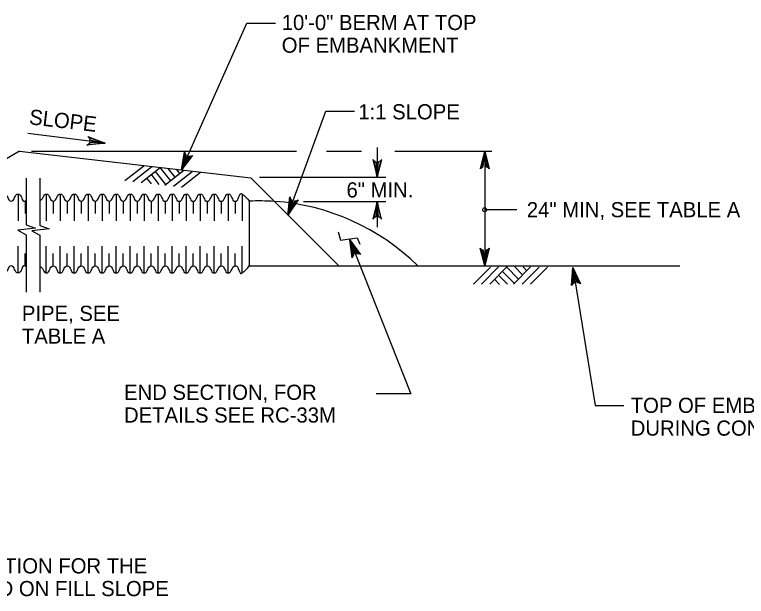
# Model space of a CAD drawing. Extents: x 636462 to 637367, y 299944 to 300538.
# Drawn here: x 636777.1 to 636921.8, y 300064.4 to 300179.4 of the extents above; entities that cross this region are included whole.
import ezdxf

# ---------------------------------------------------------------- set-up
doc = ezdxf.new("R2010")
doc.units = 0
doc.layers.add('1', color=7, linetype='Continuous')
doc.layers.add('Default', color=7, linetype='Continuous')

# ---------------------------------------------------------------- blocks, each defined once
blk = doc.blocks.new('SC9446')
at = {"layer": 'Default'}
blk.add_line((0, 0), (0, 0), dxfattribs=at)

msp = doc.modelspace()

# ---------------------------------------------------------------- linework, layer by layer
at = {"layer": '1'}
msp.add_line((636843.37, 300134.93), (636855.42, 300104.46), dxfattribs=at)
msp.add_lwpolyline([(636841.04, 300136.46), (636841.54, 300134.84), (636844.79, 300135.33), (636845.36, 300134.04)], dxfattribs=at)
at = {"layer": 'Default'}
for p, q in [((636810.07, 300148.74), (636823.01, 300177.78)), ((636823.01, 300177.78), (636828.69, 300177.78)), ((636778.09, 300152.42), (636723.37, 300120.94)), ((636778.09, 300152.42), (636823.79, 300147.16)), ((636780.41, 300152.42), (636832.84, 300152.42)), ((636838.75, 300152.42), (636845.69, 300152.42)), ((636848.79, 300153.14), (636848.79, 300147.3)), ((636852.29, 300152.42), (636871.44, 300152.42)), ((636870.03, 300152.42), (636870.03, 300129.76)), ((636798.92, 300146.61), (636802.66, 300149.57)), ((636800.49, 300146.43), (636804.24, 300149.41)), ((636802.11, 300146.24), (636805.86, 300149.22)), ((636804.88, 300148.44), (636806.94, 300145.85)), ((636805.79, 300149.23), (636807.9, 300146.58)), ((636806.77, 300145.7), (636810.55, 300148.7)), ((636807.41, 300149.04), (636808.78, 300147.32)), ((636808.48, 300145.51), (636812.2, 300148.45)), ((636809.05, 300148.85), (636809.71, 300148.03)), ((636810.1, 300145.32), (636813.82, 300148.27)), ((636779.38, 300147.1), (636779.38, 300137.86)), ((636782.11, 300147.1), (636782.11, 300137.76)), ((636803.17, 300147.09), (636804.07, 300145.96)), ((636804.08, 300147.8), (636805.64, 300145.83)), ((636823.79, 300147.16), (636841.18, 300129.76)), ((636825.49, 300147.3), (636850.48, 300147.3)), ((636777.8, 300143.94), (636777.8, 300138.68)), ((636783.34, 300143.94), (636783.34, 300138.68)), ((636786.11, 300143.94), (636786.11, 300138.68)), ((636788.88, 300143.94), (636788.88, 300138.68)), ((636791.65, 300143.94), (636791.65, 300138.68)), ((636794.42, 300143.94), (636794.42, 300138.68)), ((636797.19, 300143.94), (636797.19, 300138.68)), ((636799.96, 300143.94), (636799.96, 300138.68)), ((636802.73, 300143.94), (636802.73, 300138.68)), ((636805.5, 300143.94), (636805.5, 300138.68)), ((636808.27, 300143.94), (636808.27, 300138.68)), ((636811.04, 300143.94), (636811.04, 300138.68)), ((636813.81, 300143.94), (636813.81, 300138.68)), ((636816.58, 300143.94), (636816.58, 300138.68)), ((636819.35, 300143.94), (636819.35, 300138.68)), ((636822.12, 300143.94), (636822.12, 300138.68)), ((636779.19, 300142.56), (636779.19, 300140.14)), ((636784.73, 300142.56), (636784.73, 300140.14)), ((636787.5, 300142.56), (636787.5, 300140.14)), ((636790.27, 300142.56), (636790.27, 300140.14)), ((636793.04, 300142.56), (636793.04, 300140.14)), ((636795.81, 300142.56), (636795.81, 300140.14)), ((636798.58, 300142.56), (636798.58, 300140.14)), ((636801.35, 300142.56), (636801.35, 300140.14)), ((636804.12, 300142.56), (636804.12, 300140.14)), ((636806.89, 300142.55), (636806.89, 300140.14)), ((636809.66, 300142.55), (636809.66, 300140.14)), ((636812.43, 300142.55), (636812.43, 300140.14)), ((636815.2, 300142.55), (636815.2, 300140.14)), ((636817.96, 300142.55), (636817.96, 300140.14)), ((636820.73, 300142.55), (636820.73, 300140.14)), ((636823.5, 300142.55), (636823.5, 300129.76)), ((636823.5, 300142.55), (636823.5, 300129.76)), ((636834.21, 300142.5), (636850.48, 300142.5)), ((636848.79, 300142.5), (636848.79, 300137.4)), ((636876.41, 300140.85), (636870.03, 300140.85)), ((636779.38, 300135.93), (636779.38, 300124.53)), ((636782.11, 300135.83), (636782.11, 300124.53)), ((636777.8, 300128.38), (636777.8, 300133.64)), ((636783.34, 300128.38), (636783.34, 300133.64)), ((636786.11, 300128.38), (636786.11, 300133.64)), ((636788.88, 300128.38), (636788.88, 300133.64)), ((636791.65, 300128.38), (636791.65, 300133.64)), ((636794.42, 300128.38), (636794.42, 300133.64)), ((636797.19, 300128.38), (636797.19, 300133.64)), ((636799.96, 300128.38), (636799.96, 300133.64)), ((636802.73, 300128.38), (636802.73, 300133.64)), ((636805.5, 300128.38), (636805.5, 300133.64)), ((636808.27, 300128.38), (636808.27, 300133.64)), ((636811.04, 300128.38), (636811.04, 300133.64)), ((636813.81, 300128.38), (636813.81, 300133.64)), ((636816.58, 300128.38), (636816.58, 300133.64)), ((636819.35, 300128.38), (636819.35, 300133.64)), ((636822.12, 300128.38), (636822.12, 300133.64)), ((636779.19, 300129.76), (636779.19, 300132.18)), ((636784.73, 300129.76), (636784.73, 300132.18)), ((636787.5, 300129.76), (636787.5, 300132.18)), ((636790.27, 300129.76), (636790.27, 300132.18)), ((636793.04, 300129.76), (636793.04, 300132.18)), ((636795.81, 300129.76), (636795.81, 300132.18)), ((636798.58, 300129.76), (636798.58, 300132.18)), ((636801.35, 300129.76), (636801.35, 300132.18)), ((636804.12, 300129.76), (636804.12, 300132.18)), ((636806.89, 300129.76), (636806.89, 300132.18)), ((636809.66, 300129.76), (636809.66, 300132.18)), ((636812.43, 300129.76), (636812.43, 300132.18)), ((636815.2, 300129.76), (636815.2, 300132.18)), ((636817.96, 300129.76), (636817.96, 300132.18)), ((636820.73, 300129.76), (636820.73, 300132.18)), ((636823.5, 300129.76), (636841.18, 300129.76)), ((636841.18, 300129.76), (636908.62, 300129.76)), ((636842.95, 300129.76), (636852.95, 300129.76)), ((636867.81, 300126.16), (636871.18, 300129.53)), ((636869.39, 300126.16), (636872.77, 300129.55)), ((636871.02, 300126.16), (636874.41, 300129.55)), ((636874.33, 300129.55), (636876.73, 300127.15)), ((636875.71, 300126.16), (636879.12, 300129.56)), ((636875.97, 300129.55), (636877.53, 300127.99)), ((636877.43, 300126.16), (636880.79, 300129.51)), ((636877.62, 300129.55), (636878.36, 300128.8)), ((636879.07, 300126.16), (636882.42, 300129.51)), ((636872.79, 300127.93), (636874.57, 300126.16)), ((636873.52, 300128.66), (636875.86, 300126.32)), ((636871.98, 300127.12), (636872.99, 300126.1)), ((636855.42, 300104.46), (636848.58, 300104.46))]:
    msp.add_line(p, q, dxfattribs=at)
for points in [[(636831.14, 300139.79), (636838.61, 300160.33), (636844.28, 300160.33)], [(636794.98, 300154.05), (636779.69, 300155.91)], [(636791.85, 300155.08), (636791.61, 300155.33), (636794.98, 300154.05), (636791.85, 300155.08), (636792, 300154.68), (636794.98, 300154.05), (636791.94, 300154.16), (636791.72, 300153.81), (636794.98, 300154.05), (636791.4, 300153.6), (636791.72, 300153.81)], [(636811.97, 300151.43), (636812.29, 300151.58), (636810.07, 300148.74), (636811.97, 300151.43), (636811.55, 300151.4), (636810.07, 300148.74), (636811.07, 300151.61), (636810.8, 300151.93), (636810.07, 300148.74), (636810.68, 300152.29), (636810.8, 300151.93)], [(636869.39, 300149.19), (636869.17, 300148.92), (636870.03, 300152.42), (636869.39, 300149.19), (636869.76, 300149.39), (636870.03, 300152.42), (636870.29, 300149.39), (636870.66, 300149.21), (636870.03, 300152.42), (636870.92, 300148.93), (636870.66, 300149.21)], [(636848.16, 300150.53), (636847.93, 300150.8), (636848.79, 300147.3), (636848.16, 300150.53), (636848.53, 300150.33), (636848.79, 300147.3), (636849.05, 300150.33), (636849.43, 300150.51), (636848.79, 300147.3), (636849.68, 300150.79), (636849.43, 300150.51)], [(636832.84, 300142.62), (636833.14, 300142.79), (636831.14, 300139.79), (636832.84, 300142.62), (636832.42, 300142.56), (636831.14, 300139.79), (636831.93, 300142.73), (636831.64, 300143.03), (636831.14, 300139.79), (636831.49, 300143.38), (636831.64, 300143.03)], [(636849.43, 300139.27), (636849.65, 300139), (636848.79, 300142.5), (636849.43, 300139.27), (636849.06, 300139.47), (636848.79, 300142.5), (636848.53, 300139.47), (636848.16, 300139.29), (636848.79, 300142.5), (636847.91, 300139.01), (636848.16, 300139.29)], [(636779.38, 300137.86), (636781.2, 300137.19), (636777.76, 300136.79), (636779.38, 300135.93)], [(636782.11, 300137.76), (636783.93, 300137.09), (636780.49, 300136.69), (636782.11, 300135.83)], [(636843.95, 300131.68), (636843.84, 300131.35), (636843.37, 300134.93), (636843.95, 300131.68), (636844.22, 300132), (636843.37, 300134.93), (636844.71, 300132.2), (636845.12, 300132.16), (636843.37, 300134.93), (636845.46, 300131.99), (636845.12, 300132.16)], [(636870.67, 300132.99), (636870.89, 300133.26), (636870.03, 300129.76), (636870.67, 300132.99), (636870.29, 300132.8), (636870.03, 300129.76), (636869.77, 300132.79), (636869.39, 300132.97), (636870.03, 300129.76), (636869.14, 300133.25), (636869.39, 300132.97)], [(636887.39, 300126.17), (636887.22, 300125.86), (636887.45, 300129.46), (636887.39, 300126.17), (636887.72, 300126.43), (636887.45, 300129.46), (636888.24, 300126.52), (636888.64, 300126.41), (636887.45, 300129.46), (636888.94, 300126.18), (636888.64, 300126.41)], [(636887.44, 300129.47), (636891.87, 300102.15), (636897.54, 300102.15)]]:
    msp.add_lwpolyline(points, dxfattribs=at)
msp.add_circle((636870.03, 300140.85), 0.391, dxfattribs=at)
for start, end in [(86.2211, 92.5748), (45.3846, 86.2211)]:
    msp.add_arc((636825.51, 300098.04), 44.56, start, end, dxfattribs=at)
for points in [[(636764.07, 300143.83), (636764.5, 300143.4), (636764.92, 300142.98), (636765.34, 300142.56), (636765.8, 300142.09), (636766.26, 300143.94), (636766.73, 300143.94), (636767.19, 300143.94), (636767.65, 300142.56), (636768.11, 300142.56), (636768.57, 300142.56), (636769.03, 300143.94), (636769.5, 300143.94), (636769.96, 300143.94), (636770.42, 300142.56), (636770.88, 300142.56), (636771.34, 300142.56), (636771.8, 300143.94), (636772.27, 300143.94), (636772.73, 300143.94), (636773.19, 300142.56), (636773.65, 300142.56), (636774.11, 300142.56), (636774.57, 300143.94), (636775.04, 300143.94), (636775.5, 300143.94), (636775.96, 300142.56), (636776.42, 300142.56), (636776.88, 300142.56), (636777.34, 300143.94), (636777.8, 300143.94), (636778.27, 300143.94), (636778.73, 300142.42), (636779.19, 300142.56), (636779.25, 300142.57), (636779.31, 300142.73), (636779.38, 300142.74)], [(636782.11, 300142.7), (636782.52, 300142.72), (636782.93, 300143.93), (636783.34, 300143.94), (636783.81, 300143.95), (636784.27, 300142.56), (636784.73, 300142.56), (636785.19, 300142.56), (636785.65, 300143.94), (636786.11, 300143.94), (636786.58, 300143.94), (636787.04, 300142.56), (636787.5, 300142.56), (636787.96, 300142.56), (636788.42, 300143.94), (636788.88, 300143.94), (636789.35, 300143.94), (636789.81, 300142.56), (636790.27, 300142.56), (636790.73, 300142.56), (636791.19, 300143.94), (636791.65, 300143.94), (636792.12, 300143.94), (636792.58, 300142.56), (636793.04, 300142.56), (636793.5, 300142.56), (636793.96, 300143.94), (636794.42, 300143.94), (636794.88, 300143.94), (636795.35, 300142.56), (636795.81, 300142.56), (636796.27, 300142.56), (636796.73, 300143.94), (636797.19, 300143.94), (636797.65, 300143.94), (636798.11, 300142.56), (636798.58, 300142.56), (636799.04, 300142.56), (636799.5, 300143.94), (636799.96, 300143.94), (636800.42, 300143.94), (636800.88, 300142.56), (636801.35, 300142.56), (636801.81, 300142.56), (636802.27, 300143.94), (636802.73, 300143.94), (636803.19, 300143.94), (636803.65, 300142.56), (636804.12, 300142.56), (636804.58, 300142.56), (636805.04, 300143.94), (636805.5, 300143.94), (636805.96, 300143.94), (636806.42, 300142.55), (636806.89, 300142.55), (636807.35, 300142.55), (636807.81, 300143.94), (636808.27, 300143.94), (636808.73, 300143.94), (636809.19, 300142.55), (636809.66, 300142.55), (636810.12, 300142.55), (636810.58, 300143.94), (636811.04, 300143.94), (636811.5, 300143.94), (636811.96, 300142.55), (636812.43, 300142.55), (636812.89, 300142.55), (636813.35, 300143.94), (636813.81, 300143.94), (636814.27, 300143.94), (636814.73, 300142.55), (636815.2, 300142.55), (636815.66, 300142.55), (636816.12, 300143.94), (636816.58, 300143.94), (636817.04, 300143.94), (636817.5, 300142.55), (636817.96, 300142.55), (636818.43, 300142.55), (636818.89, 300143.94), (636819.35, 300143.94), (636819.81, 300143.94), (636820.27, 300142.55), (636820.73, 300142.55), (636821.2, 300142.55), (636821.66, 300144.27), (636822.12, 300143.94), (636822.58, 300143.61), (636823.04, 300143.17), (636823.5, 300142.55)], [(636779.38, 300129.58), (636779.31, 300129.59), (636779.25, 300129.75), (636779.19, 300129.76), (636778.73, 300129.9), (636778.27, 300128.38), (636777.8, 300128.38), (636777.34, 300128.38), (636776.88, 300129.76), (636776.42, 300129.76), (636775.96, 300129.76), (636775.5, 300128.38), (636775.04, 300128.38), (636774.57, 300128.38), (636774.11, 300129.76), (636773.65, 300129.76), (636773.19, 300129.76), (636772.73, 300128.38), (636772.27, 300128.38), (636771.8, 300128.38), (636771.34, 300129.76), (636770.88, 300129.76), (636770.42, 300129.76), (636769.96, 300128.38), (636769.5, 300128.38), (636769.03, 300128.38), (636768.57, 300129.76), (636768.11, 300129.76), (636767.65, 300129.76), (636767.19, 300128.38), (636766.73, 300128.38), (636766.26, 300128.38), (636765.8, 300129.76), (636765.34, 300129.76), (636764.88, 300129.76), (636764.42, 300128.38), (636763.96, 300128.38), (636763.5, 300128.38), (636763.03, 300129.76), (636762.57, 300129.76), (636762.11, 300129.76), (636761.65, 300128.38), (636761.19, 300128.38), (636760.72, 300128.38), (636760.26, 300129.76), (636759.8, 300129.76), (636759.34, 300129.76), (636758.88, 300128.05), (636758.42, 300128.38), (636757.96, 300128.71), (636757.49, 300129.15), (636757.03, 300129.76)], [(636782.11, 300129.61), (636782.52, 300129.6), (636782.93, 300128.39), (636783.34, 300128.38), (636783.81, 300128.37), (636784.27, 300129.76), (636784.73, 300129.76), (636785.19, 300129.76), (636785.65, 300128.38), (636786.11, 300128.38), (636786.58, 300128.38), (636787.04, 300129.76), (636787.5, 300129.76), (636787.96, 300129.76), (636788.42, 300128.38), (636788.88, 300128.38), (636789.35, 300128.38), (636789.81, 300129.76), (636790.27, 300129.76), (636790.73, 300129.76), (636791.19, 300128.38), (636791.65, 300128.38), (636792.12, 300128.38), (636792.58, 300129.76), (636793.04, 300129.76), (636793.5, 300129.76), (636793.96, 300128.38), (636794.42, 300128.38), (636794.88, 300128.38), (636795.35, 300129.76), (636795.81, 300129.76), (636796.27, 300129.76), (636796.73, 300128.38), (636797.19, 300128.38), (636797.65, 300128.38), (636798.11, 300129.76), (636798.58, 300129.76), (636799.04, 300129.76), (636799.5, 300128.38), (636799.96, 300128.38), (636800.42, 300128.38), (636800.88, 300129.76), (636801.35, 300129.76), (636801.81, 300129.76), (636802.27, 300128.38), (636802.73, 300128.38), (636803.19, 300128.38), (636803.65, 300129.76), (636804.12, 300129.76), (636804.58, 300129.76), (636805.04, 300128.38), (636805.5, 300128.38), (636805.96, 300128.38), (636806.42, 300129.76), (636806.89, 300129.76), (636807.35, 300129.76), (636807.81, 300128.38), (636808.27, 300128.38), (636808.73, 300128.38), (636809.19, 300129.76), (636809.66, 300129.76), (636810.12, 300129.76), (636810.58, 300128.38), (636811.04, 300128.38), (636811.5, 300128.38), (636811.96, 300129.76), (636812.43, 300129.76), (636812.89, 300129.76), (636813.35, 300128.38), (636813.81, 300128.38), (636814.27, 300128.38), (636814.73, 300129.76), (636815.2, 300129.76), (636815.66, 300129.76), (636816.12, 300128.38), (636816.58, 300128.38), (636817.04, 300128.38), (636817.5, 300129.76), (636817.96, 300129.76), (636818.43, 300129.76), (636818.89, 300128.38), (636819.35, 300128.38), (636819.81, 300128.38), (636820.27, 300129.76), (636820.73, 300129.76), (636821.2, 300129.76), (636821.66, 300128.05), (636822.12, 300128.38), (636822.58, 300128.71), (636823.04, 300129.15), (636823.5, 300129.76)]]:
    msp.add_open_spline(points, degree=3, dxfattribs=at)

# ---------------------------------------------------------------- block references
at = {"layer": 'Default', "xscale": 2.753831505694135, "yscale": 2.753831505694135}
for p in [(636779.38, 300142.74), (636782.11, 300142.71), (636779.38, 300129.58), (636782.11, 300129.62)]:
    msp.add_blockref('SC9446', p, dxfattribs=at)

# ---------------------------------------------------------------- texts
at = {"layer": 'Default'}
for s, p in [('10\'-0" BERM AT TOP', (636829.91, 300176.39)), ('OF EMBANKMENT', (636829.91, 300171.9)), ('1:1 SLOPE', (636845.05, 300158.73)), ('6" MIN.', (636842.71, 300143.28)), ('24" MIN, SEE TABLE A', (636878.36, 300139.37)), ('PIPE, SEE', (636778.54, 300118.88)), ('TABLE A', (636778.54, 300114.38)), ('END SECTION, FOR', (636798.73, 300103.27)), ('TOP OF EMBANKMENT', (636898.9, 300100.69)), ('DETAILS SEE RC-33M', (636798.73, 300098.77)), ('DURING CONSTRUCTION', (636898.9, 300096.19)), ('SUITABLE CONNECTION FOR THE', (636737.18, 300068.95)), ('TYPE OF PIPE USED ON FILL SLOPE', (636737.18, 300064.46))]:
    msp.add_text(s, height=2.998, dxfattribs=at).set_placement(p)
msp.add_text('SLOPE', height=2.998, rotation=353.4271, dxfattribs=at).set_placement((636779.86, 300157.77))

doc.saveas('drawing.dxf')
